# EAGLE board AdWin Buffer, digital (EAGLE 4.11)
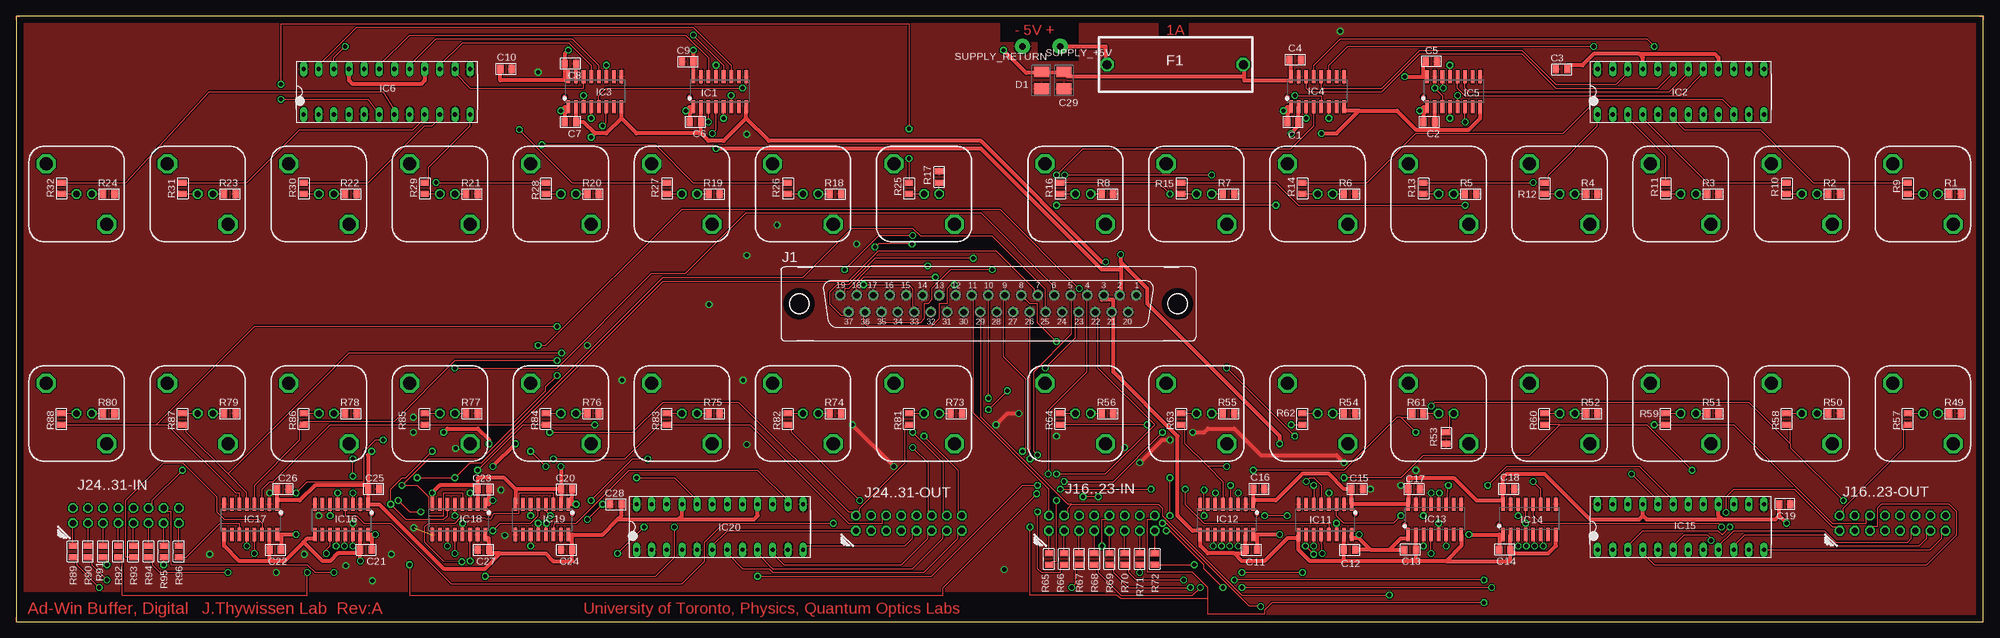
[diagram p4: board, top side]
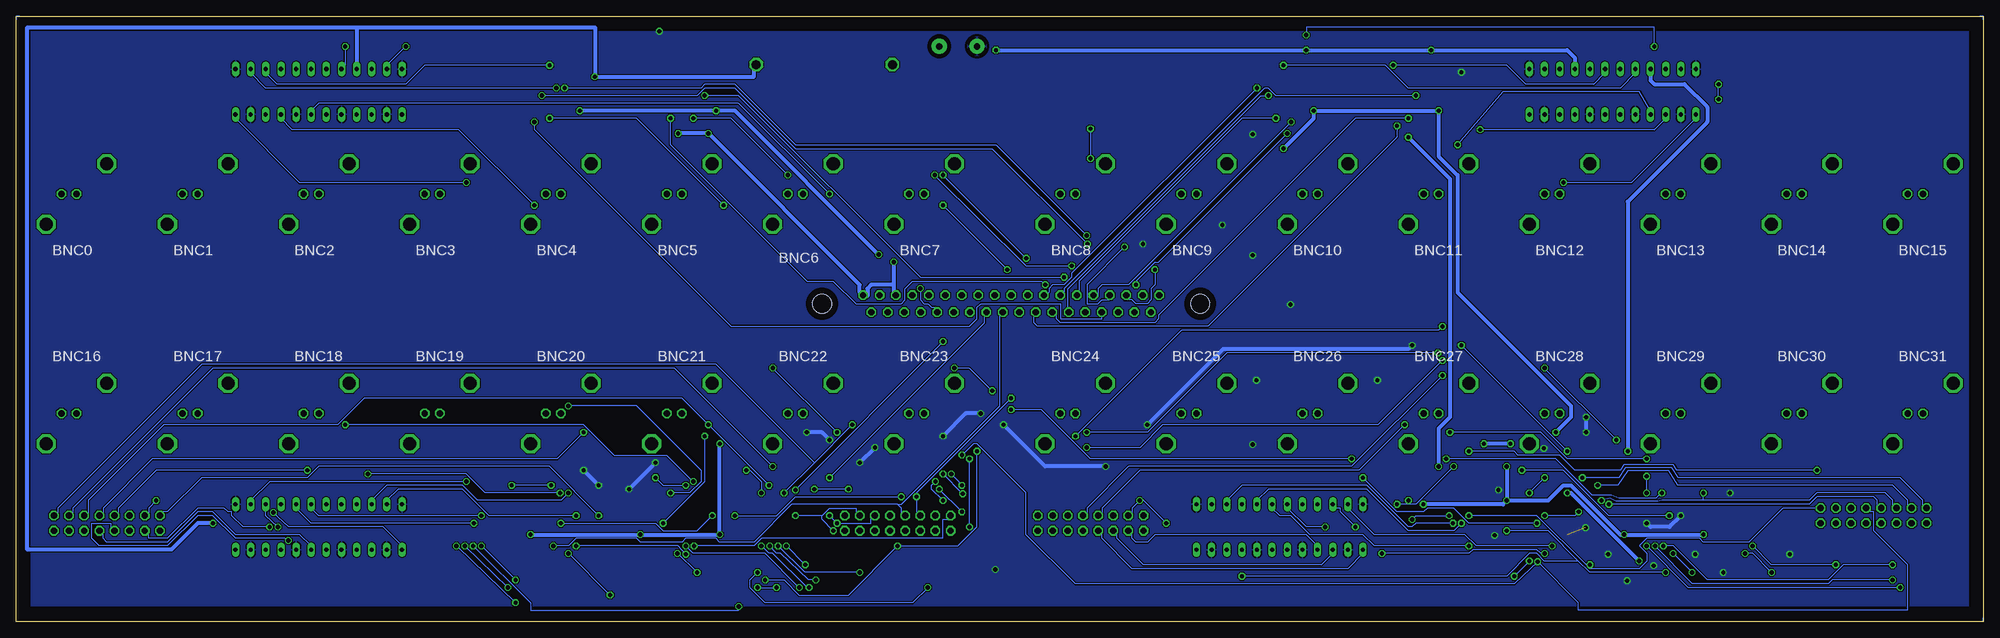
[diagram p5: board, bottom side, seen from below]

Size 330.2 x 101.6 mm. Coordinates in mm from the lower left corner, seen from the top.
Outline: 0,0 330.2,0 330.2,101.6 0,101.6 0,0
Copper layers (1*16): Top 0.035mm / dielectric 1.5mm / Bottom 0.035mm
Design rules "default": minimum track width 8mil, minimum drill 24mil, track to track 8mil, track to pad 8mil, pad to pad 8mil, via to via 8mil, smd to smd 8mil, copper to edge 40mil, drill to drill 8mil, minimum pad ring 10mil, minimum via ring 8mil, stop-mask expansion 4mil, vias tented up to drill 0mil, thermal gap 10mil
Net classes: 1 Pwr/Gnd .016"w: width 0.406 mm; 2 Pwr/Gnd .025"w: width 0.635 mm

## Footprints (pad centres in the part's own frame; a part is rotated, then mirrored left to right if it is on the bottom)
CONN-BNC-AMPHENOL-TYPE1 = drill 1.067 octagon: CONDUCTOR 0,0; SHIELD -2.54,0 | drill 2.184 octagon: MTG1 -5.08,-5.08; MTG2 5.08,5.08
0805 = smd 1.016 x 1.397: 1 -1.905,0; 2 0,0
EIA-B = smd 1.778 x 2.54: 1 -1.4,0; 2 1.4,0
FUSE5X20-2 = drill 1.511 octagon: 1 -10.16,0; 2 12.7,0
SOIC-16 = smd 0.6 x 2.2: 1 -3.81,-2.54; 2 -2.54,-2.54; 3 -1.27,-2.54; 4 0,-2.54; 5 1.27,-2.54; 6 2.54,-2.54; 7 3.81,-2.54; 8 5.08,-2.54; 9 5.08,2.54; 10 3.81,2.54; 11 2.54,2.54; 12 1.27,2.54; 13 0,2.54; 14 -1.27,2.54; 15 -2.54,2.54; 16 -3.81,2.54
DIL24 = drill 0.711 long: 1 -11.43,-3.81; 2 -8.89,-3.81; 3 -6.35,-3.81; 4 -3.81,-3.81; 5 -1.27,-3.81; 6 1.27,-3.81; 7 3.81,-3.81; 8 6.35,-3.81; 9 8.89,-3.81; 10 11.43,-3.81; 11 13.97,-3.81; 12 16.51,-3.81; 13 16.51,3.81; 14 13.97,3.81; 15 11.43,3.81; 16 8.89,3.81; 17 6.35,3.81; 18 3.81,3.81; 19 1.27,3.81; 20 -1.27,3.81; 21 -3.81,3.81; 22 -6.35,3.81; 23 -8.89,3.81; 24 -11.43,3.81
F37V = drill 1.067 octagon: 1 24.841,1.422; 2 22.073,1.422; 3 19.329,1.422; 4 16.561,1.422; 5 13.792,1.422; 6 11.049,1.422; 7 8.28,1.422; 8 5.512,1.422; 9 2.769,1.422; 10 0,1.422; 11 -2.769,1.422; 12 -5.512,1.422; 13 -8.28,1.422; 14 -11.049,1.422; 15 -13.818,1.422; 16 -16.561,1.422; 17 -19.329,1.422; 18 -22.098,1.422; 19 -24.841,1.422; 20 23.47,-1.422; 21 20.701,-1.422; 22 17.932,-1.422; 23 15.189,-1.422; 24 12.421,-1.422; 25 9.652,-1.422; 26 6.909,-1.422; 27 4.14,-1.422; 28 1.372,-1.422; 29 -1.372,-1.422; 30 -4.14,-1.422; 31 -6.909,-1.422; 32 -9.677,-1.422; 33 -12.421,-1.422; 34 -15.189,-1.422; 35 -17.958,-1.422; 36 -20.701,-1.422; 37 -23.47,-1.422 | hole 3.175: 31.75,0; -31.75,0
JUMPER-2X8 = drill 1.067 octagon: 1 -1.27,7.62; 2 -1.27,5.08; 3 -1.27,2.54; 4 -1.27,0; 5 -1.27,-2.54; 6 -1.27,-5.08; 7 -1.27,-7.62; 8 -1.27,-10.16; 9 1.27,7.62; 10 1.27,5.08; 11 1.27,2.54; 12 1.27,0; 13 1.27,-2.54; 14 1.27,-5.08; 15 1.27,-7.62; 16 1.27,-10.16
TP-HOLE = drill 1.067 pad 2.54 round: P$1 0,0

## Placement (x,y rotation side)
BNC0  AMP 227673-1  [CONN-BNC-AMPHENOL-TYPE1]  320.04,71.75 0 bottom
BNC1  [CONN-BNC-AMPHENOL-TYPE1]  299.72,71.75 0 bottom
BNC2  [CONN-BNC-AMPHENOL-TYPE1]  279.4,71.75 0 bottom
BNC3  [CONN-BNC-AMPHENOL-TYPE1]  259.08,71.75 0 bottom
BNC4  [CONN-BNC-AMPHENOL-TYPE1]  238.76,71.75 0 bottom
BNC5  [CONN-BNC-AMPHENOL-TYPE1]  218.44,71.75 0 bottom
BNC6  [CONN-BNC-AMPHENOL-TYPE1]  198.12,71.75 0 bottom
BNC7  [CONN-BNC-AMPHENOL-TYPE1]  177.8,71.75 0 bottom
BNC8  AMP 227673-1  [CONN-BNC-AMPHENOL-TYPE1]  152.4,71.75 0 bottom
BNC9  [CONN-BNC-AMPHENOL-TYPE1]  132.08,71.75 0 bottom
BNC10  [CONN-BNC-AMPHENOL-TYPE1]  111.76,71.75 0 bottom
BNC11  [CONN-BNC-AMPHENOL-TYPE1]  91.44,71.75 0 bottom
BNC12  [CONN-BNC-AMPHENOL-TYPE1]  71.12,71.75 0 bottom
BNC13  [CONN-BNC-AMPHENOL-TYPE1]  50.8,71.75 0 bottom
BNC14  [CONN-BNC-AMPHENOL-TYPE1]  30.48,71.75 0 bottom
BNC15  [CONN-BNC-AMPHENOL-TYPE1]  10.16,71.75 0 bottom
BNC16  AMP 227673-1  [CONN-BNC-AMPHENOL-TYPE1]  320.04,34.92 0 bottom
BNC17  [CONN-BNC-AMPHENOL-TYPE1]  299.72,34.92 0 bottom
BNC18  [CONN-BNC-AMPHENOL-TYPE1]  279.4,34.92 0 bottom
BNC19  [CONN-BNC-AMPHENOL-TYPE1]  259.08,34.92 0 bottom
BNC20  [CONN-BNC-AMPHENOL-TYPE1]  238.76,34.92 0 bottom
BNC21  [CONN-BNC-AMPHENOL-TYPE1]  218.44,34.92 0 bottom
BNC22  [CONN-BNC-AMPHENOL-TYPE1]  198.12,34.92 0 bottom
BNC23  [CONN-BNC-AMPHENOL-TYPE1]  177.8,34.92 0 bottom
BNC24  AMP 227673-1  [CONN-BNC-AMPHENOL-TYPE1]  152.4,34.92 0 bottom
BNC25  [CONN-BNC-AMPHENOL-TYPE1]  132.08,34.92 0 bottom
BNC26  [CONN-BNC-AMPHENOL-TYPE1]  111.76,34.92 0 bottom
BNC27  [CONN-BNC-AMPHENOL-TYPE1]  91.44,34.92 0 bottom
BNC28  [CONN-BNC-AMPHENOL-TYPE1]  71.12,34.92 0 bottom
BNC29  [CONN-BNC-AMPHENOL-TYPE1]  50.8,34.92 0 bottom
BNC30  [CONN-BNC-AMPHENOL-TYPE1]  30.48,34.92 0 bottom
BNC31  [CONN-BNC-AMPHENOL-TYPE1]  10.16,34.92 0 bottom
C1  0.1uF  [0805]  213.36,83.82 180 top
C2  [0805]  236.22,83.82 180 top
C3  0.1uF  [0805]  260.35,92.71 0 top
C4  [0805]  213.74,94.23 180 top
C5  [0805]  236.6,93.98 180 top
C6  0.1uF  [0805]  113.03,83.82 180 top
C7  [0805]  92.08,83.82 180 top
C8  0.1uF  [0805]  92.08,93.6 180 top
C9  [0805]  113.67,93.98 0 top
C10  [0805]  81.28,92.71 180 top
C11  0.1uF  [0805]  208.28,12.06 0 top
C12  [0805]  224.79,12.06 0 top
C13  [0805]  233.04,12.06 180 top
C14  [0805]  248.92,12.06 180 top
C15  0.1uF  [0805]  224.16,22.23 180 top
C16  [0805]  207.65,22.23 180 top
C17  [0805]  233.68,22.23 180 top
C18  [0805]  249.56,22.23 180 top
C19  [0805]  295.91,19.68 180 top
C20  0.1uF  [0805]  93.34,22.23 0 top
C21  [0805]  59.69,12.06 0 top
C22  [0805]  44.45,12.06 0 top
C23  [0805]  79.38,22.23 0 top
C24  0.1uF  [0805]  93.34,12.06 0 top
C25  [0805]  59.05,22.23 180 top
C26  [0805]  43.81,22.23 180 top
C27  [0805]  79.38,12.06 0 top
C28  [0805]  101.6,19.68 0 top
C29  10uF  [EIA-B]  175.9,90.81 90 top
D1  1N????  [EIA-B]  172.09,90.81 90 top
F1  1A  [FUSE5X20-2]  195.83,93.47 180 top
IC1  [SOIC-16]  117.47,88.9 0 top
IC2  [DIL24]  276.86,88.9 0 top
IC3  [SOIC-16]  96.52,88.9 0 top
IC4  [SOIC-16]  217.81,88.9 0 top
IC5  [SOIC-16]  240.66,88.9 0 top
IC6  [DIL24]  59.69,88.9 0 top
IC11  [SOIC-16]  220.34,17.14 180 top
IC12  [SOIC-16]  203.84,17.14 180 top
IC13  [SOIC-16]  237.49,17.14 0 top
IC14  [SOIC-16]  253.37,17.14 0 top
IC15  [DIL24]  276.86,15.88 0 top
IC16  [SOIC-16]  55.24,17.14 180 top
IC17  [SOIC-16]  40.01,17.14 180 top
IC18  [SOIC-16]  74.93,17.14 180 top
IC19  [SOIC-16]  88.9,17.14 180 top
IC20  [DIL24]  115.57,15.88 0 top
J1  Wickmann #647  [F37V]  163.19,53.34 0 top
J16..23-IN  JUMPER-2X8  [JUMPER-2X8]  180.97,16.51 90 top
J16..23-OUT  JUMPER-2X8  [JUMPER-2X8]  313.69,16.51 90 top
J24..31-IN  JUMPER-2X8  [JUMPER-2X8]  17.14,17.78 90 top
J24..31-OUT  JUMPER-2X8  [JUMPER-2X8]  148.59,16.51 90 top
R1  4.3  [0805]  326.39,71.75 0 top
R2  4.3  [0805]  306.07,71.75 0 top
R3  4.3  [0805]  285.75,71.75 0 top
R4  4.3  [0805]  265.43,71.75 0 top
R5  4.3  [0805]  245.11,71.75 0 top
R6  4.3  [0805]  224.79,71.75 0 top
R7  4.3  [0805]  204.47,71.75 0 top
R8  4.3  [0805]  184.15,71.75 0 top
R9  43  [0805]  317.5,71.75 270 top
R10  43  [0805]  297.18,71.75 270 top
R11  43  [0805]  276.86,71.75 270 top
R12  43  [0805]  256.54,71.75 270 top
R13  43  [0805]  236.22,71.75 270 top
R14  43  [0805]  215.9,71.75 270 top
R15  43  [0805]  195.58,71.75 270 top
R16  43  [0805]  175.26,71.75 270 top
R17  4.3  [0805]  154.94,75.56 90 top
R18  4.3  [0805]  138.43,71.75 0 top
R19  4.3  [0805]  118.11,71.75 0 top
R20  4.3  [0805]  97.79,71.75 0 top
R21  4.3  [0805]  77.47,71.75 0 top
R22  4.3  [0805]  57.15,71.75 0 top
R23  4.3  [0805]  36.83,71.75 0 top
R24  4.3  [0805]  16.51,71.75 0 top
R25  43  [0805]  149.86,71.75 270 top
R26  43  [0805]  129.54,71.75 270 top
R27  43  [0805]  109.22,71.75 270 top
R28  43  [0805]  88.9,71.75 270 top
R29  43  [0805]  68.58,71.75 270 top
R30  43  [0805]  48.26,71.75 270 top
R31  43  [0805]  27.94,71.75 270 top
R32  43  [0805]  7.62,71.75 270 top
R49  4.3  [0805]  326.39,34.92 0 top
R50  4.3  [0805]  306.07,34.92 0 top
R51  4.3  [0805]  285.75,34.92 0 top
R52  4.3  [0805]  265.43,34.92 0 top
R53  4.3  [0805]  240.03,29.84 270 top
R54  4.3  [0805]  224.79,34.92 0 top
R55  4.3  [0805]  204.47,34.92 0 top
R56  4.3  [0805]  184.15,34.92 0 top
R57  43  [0805]  317.5,34.92 90 top
R58  43  [0805]  297.18,34.92 90 top
R59  43  [0805]  276.86,34.92 90 top
R60  43  [0805]  256.54,34.92 90 top
R61  43  [0805]  236.22,34.92 0 top
R62  43  [0805]  215.9,34.92 90 top
R63  43  [0805]  195.58,34.92 90 top
R64  43  [0805]  175.26,34.92 90 top
R65  2K  [0805]  173.35,11.43 90 top
R66  [0805]  175.9,11.43 90 top
R67  [0805]  178.44,11.43 90 top
R68  [0805]  180.97,11.43 90 top
R69  [0805]  183.51,11.43 90 top
R70  [0805]  186.06,11.43 90 top
R71  [0805]  188.59,11.43 90 top
R72  [0805]  191.13,11.43 90 top
R73  4.3  [0805]  158.75,34.92 0 top
R74  4.3  [0805]  138.43,34.92 0 top
R75  4.3  [0805]  118.11,34.92 0 top
R76  4.3  [0805]  97.79,34.92 0 top
R77  4.3  [0805]  77.47,34.92 0 top
R78  4.3  [0805]  57.15,34.92 0 top
R79  4.3  [0805]  36.83,34.92 0 top
R80  4.3  [0805]  16.51,34.92 0 top
R81  43  [0805]  149.86,34.92 90 top
R82  43  [0805]  129.54,34.92 90 top
R83  43  [0805]  109.22,34.92 90 top
R84  43  [0805]  88.9,34.92 90 top
R85  43  [0805]  68.58,34.92 90 top
R86  43  [0805]  48.26,34.92 90 top
R87  43  [0805]  27.94,34.92 90 top
R88  43  [0805]  7.62,34.92 90 top
R89  2K  [0805]  9.53,12.7 90 top
R90  [0805]  12.06,12.7 90 top
R91  [0805]  14.61,12.7 90 top
R92  [0805]  17.14,12.7 90 top
R93  [0805]  19.68,12.7 90 top
R94  [0805]  22.23,12.7 90 top
R95  [0805]  24.77,12.7 90 top
R96  [0805]  27.3,12.7 90 top
SUPPLY_+5V  [TP-HOLE]  175.26,96.52 0 top
SUPPLY_RETURN  [TP-HOLE]  168.91,96.52 0 top
U$5  [TARGET]  not placed on the board
U$7  [TARGET]  not placed on the board
U$8  [TARGET]  not placed on the board
U$9  [TITLEBLOCK_PCB]  not placed on the board

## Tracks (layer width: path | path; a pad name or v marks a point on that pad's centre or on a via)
+5V  (via drill 0.71)
  Top 0.635: 295.91,17.78 295.27,17.14 286.38,17.14 | 286.38,17.14 285.75,17.78 IC15.16 | 295.91,17.78 C19.2 | 273.05,17.78 273.69,17.14 286.38,17.14 | 273.05,17.78 IC15.21 | 249.56,20.32 C18.2 249.56,24.13 250.19,24.77 256.54,24.77 264.16,17.14 272.42,17.14 273.05,17.78 | 207.65,20.32 C16.2 | 207.65,20.32 211.46,20.32 215.9,24.77 220.34,24.77 222.88,22.23 C15.2 IC11.1 IC13.16 C17.2 233.68,24.13 241.3,24.13 245.11,20.32 249.56,20.32 | 207.65,20.32 IC12.1 | 249.56,20.32 IC14.16 | 43.81,20.32 C26.2 | 43.81,20.32 47.62,20.32 50.16,22.86 59.05,22.86 | 43.81,20.32 IC17.1 | IC18.16 78.74,13.97 79.38,13.97 C27.2 79.38,11.43 81.28,11.43 | 93.34,14.61 IC19.16 | 93.34,14.61 C24.2 93.34,10.16 90.17,10.16 88.9,11.43 81.28,11.43 | 100.97,17.14 98.42,14.61 93.34,14.61 | 100.97,17.14 101.6,17.78 C28.2 | 111.12,17.14 111.76,17.78 IC20.21 | 100.97,17.14 111.12,17.14 | 111.12,17.14 123.83,17.14 124.46,17.78 IC20.16 | 81.28,11.43 78.74,8.89 71.75,8.89 60.96,19.68 IC16.1 C25.2 59.05,22.86 | IC6.21 55.88,90.81 56.52,90.17 67.94,90.17 68.58,90.81 IC6.16 | IC1.16 C9.2 v113.67,95.89 | 92.08,90.81 92.71,90.81 IC3.16 | 92.08,90.81 81.28,90.81 C10.2 | 92.08,90.81 C8.2 92.08,95.25 v92.71,95.89 | 272.42,95.25 264.8,95.25 262.89,93.34 260.35,93.34 C3.2 | 272.42,95.25 273.05,94.61 IC2.21 | 272.42,95.25 285.12,95.25 285.75,94.61 IC2.16 | 236.22,91.44 236.22,93.34 C5.2 | 236.22,91.44 IC5.16 | C4.2 214,93.34 IC4.16 214,90.81 206.12,90.81 206.08,91.57 | F1.1 206.08,91.57 | v233.04,91.44 236.22,91.44 | v165.74,95.89 169.54,92.08 171.45,92.08 D1.2 172.72,92.08 175.26,92.08 C29.2 176.53,91.44 205.99,91.44 206.08,91.57 | 59.05,22.86 59.05,27.94 v59.69,28.57
  Top 0.635: 295.91,17.78 v297.18,16.51
  Bottom 0.635: IC6.16 68.58,94.61 69.85,95.89 v92.71,95.89 v113.67,95.89 v165.74,95.89 | 273.05,99.69 233.04,99.69 v233.04,91.44 206.38,91.44 206.38,93.34 F1.1 | 273.05,99.69 IC2.21 | v59.69,28.57 59.69,70.48 46.35,83.82 46.35,86.36 50.16,90.17 55.24,90.17 55.88,90.81 IC6.21 | v297.18,16.51 299.72,16.51 304.17,12.06 328.3,12.06 328.3,99.69 273.05,99.69
AGND  (via drill 0.71)  (1 unrouted)
  Top 0.635: v222.88,26.67 221.62,27.94 208.91,27.94 204.47,32.38 200.03,32.38 199.39,31.75 v197.49,31.75 | v193.68,30.48 192.41,30.48 v188.59,26.67 | v168.28,34.92 166.37,34.92 v164.47,33.02 | v140.34,33.02 v147.32,26.04
  Bottom 0.635: v232.41,22.86 v234.95,25.4 | v222.88,26.67 v227.33,22.23 | v197.49,31.75 194.94,31.75 v193.68,30.48 | v186.06,29.21 v188.59,26.67 | v174.62,31.11 170.81,34.92 v168.28,34.92 | v164.47,33.02 157.48,26.04 v147.32,26.04 | v140.34,33.02 127.64,45.72 96.52,45.72 v95.89,46.35 | v66.67,31.75 v66.67,34.29 | v50.8,17.78 52.7,15.88 55.88,15.88 v56.52,16.51
  other vias: 42.55,21.59 222.25,99.06 116.31,53.2 122.66,61.46 122.03,40.5 101.71,40.5 122.66,29.71 127.74,66.54 87.61,92.19 122.66,81.78 141.08,63.36 165.84,8.75 62.97,11.29 59.8,6.85 32.49,11.29 48.37,11.29 82.02,14.47 73.77,29.07 55.35,9.39 43.67,8.24 66.78,15.74 81.39,22.09
  pour Top: 1.27,100.33 1.27,5.08 182.88,5.08 182.88,1.27 328.93,1.27 328.93,100.33 196.85,100.33 196.85,97.79 191.77,97.79 191.77,100.33 178.44,100.33 178.44,93.98 171.45,93.98 171.45,97.16 165.1,97.16 165.1,100.33
  pour Bottom: 2.54,99.06 2.54,2.54 327.66,2.54 327.66,99.06
BNC0
  Top 0.203: R9.1 301.62,73.66 292.74,82.55 280.04,82.55 278.13,84.45 IC2.6
BNC1
  Top 0.203: R10.1 283.85,73.66 273.05,84.45 IC2.4
BNC2
  Top 0.203: R11.1 276.86,78.11 270.51,84.45 IC2.3
BNC3
  Top 0.203: R12.1 257.18,73.66 257.18,74.93 265.43,83.19 IC2.1
BNC4  (via drill 0.71)
  Top 0.203: R13.1 v254.63,73.66
  Bottom 0.203: v254.63,73.66 282.57,73.66 293.37,84.45 IC2.12
BNC5
  Top 0.203: R14.1 226.69,73.66 234.95,81.92 259.71,81.92 265.43,87.63 286.38,87.63 288.29,85.72 IC2.10
BNC6  (via drill 0.71)
  Top 0.203: v243.21,69.85 215.26,69.85 211.46,73.66 R15.1
  Bottom 0.203: v243.21,69.85 255.91,82.55 283.85,82.55 285.75,84.45 IC2.9
BNC7  (via drill 0.71)
  Top 0.203: v193.68,71.75 191.77,73.66 R16.1
  Bottom 0.203: v193.68,71.75 208.91,87 279.4,87 280.67,85.72 IC2.7
BNC8  (via drill 0.71)
  Top 0.203: v149.86,82.68 149.86,100.33 44.45,100.33 v44.45,90.17 | v149.86,77.72 R25.1 | v44.45,87.63 59.05,87.63 IC6.6
  Bottom 0.203: v44.45,87.63 v44.45,90.17 | v149.86,82.68 v149.86,77.72
BNC9  (via drill 0.71)
  Top 0.203: v88.27,80.01 107.31,80.01 113.67,73.66 R26.1
  Bottom 0.203: v88.27,80.01 80.64,88.9 57.78,88.9 55.88,85.72 IC6.4
BNC10  (via drill 0.71)
  Top 0.203: v84.45,82.55 93.34,73.66 R27.1
  Bottom 0.203: v84.45,82.55 55.24,82.55 53.34,84.45 IC6.3
BNC11  (via drill 0.71)
  Top 0.203: v70.48,73.66 R28.1
  Bottom 0.203: v70.48,73.66 59.05,73.66 48.26,84.45 IC6.1
BNC12
  Top 0.203: R29.1 69.22,73.66 69.22,76.2 76.2,83.19 IC6.12
BNC13
  Top 0.203: R30.1 59.05,73.66 68.58,83.19 69.85,83.19 71.12,84.45 IC6.10
BNC14
  Top 0.203: R31.1 38.73,73.66 47.62,82.55 66.67,82.55 68.58,84.45 IC6.9
BNC15
  Top 0.203: R32.1 18.41,73.66 32.38,88.9 61.59,88.9 63.5,85.72 IC6.7
BNC16  (via drill 0.71)
  Top 0.203: R57.1 316.87,33.02 316.87,29.21 306.7,19.05 306.7,17.78 J16..23-OUT.9 | v232.41,17.78 231.14,16.51 222.88,16.51 221.62,17.78 IC11.3
  Bottom 0.203: v232.41,17.78 240.66,26.04 279.4,26.04 281.31,24.13 299.08,24.13 304.8,18.41 306.07,18.41 J16..23-OUT.9
BNC17  (via drill 0.71)
  Top 0.203: 297.81,29.84 297.81,29.21 v306.7,20.32 | 297.81,29.84 297.81,33.02 R58.1 | v237.49,36.2 238.12,36.83 290.83,36.83 297.81,29.84 | v220.34,21.59 IC11.4
  Bottom 0.203: v306.7,20.32 307.98,19.05 307.98,17.78 J16..23-OUT.10 | v220.34,21.59 217.17,21.59 215.26,23.5 215.26,25.4 226.06,36.2 v237.49,36.2
BNC18  (via drill 0.71)
  Top 0.203: J16..23-OUT.11 310.51,17.78 310.51,16.51 304.8,16.51 288.29,33.02 R59.1 v274.95,33.02 | v216.53,23.5 217.17,24.13 217.81,24.13 219.07,22.86 IC11.5
  Bottom 0.203: v216.53,23.5 220.98,27.94 229.87,27.94 234.95,33.02 v274.95,33.02
BNC19  (via drill 0.71)
  Top 0.203: 259.08,33.02 273.69,33.02 v281.31,25.4 | 259.08,33.02 R60.1 | v222.88,24.13 232.41,24.13 236.22,27.94 254,27.94 259.08,33.02 | v217.81,22.86 IC11.6
  Bottom 0.203: v281.31,25.4 306.7,25.4 313.06,19.05 313.06,17.78 J16..23-OUT.12 | v217.81,22.86 221.62,22.86 v222.88,24.13
BNC20  (via drill 0.71)
  Top 0.203: 232.41,34.29 231.78,34.29 222.88,25.4 v207.65,25.4 | 232.41,34.29 234.31,34.29 R61.1 | v205.1,21.59 IC12.3 | v234.95,31.75 232.41,34.29
  Bottom 0.203: v207.65,25.4 207.01,25.4 205.1,23.5 v205.1,21.59 | v234.95,31.75 239.4,27.3 307.34,27.3 315.6,19.05 315.6,17.78 J16..23-OUT.13
BNC21  (via drill 0.71)
  Top 0.203: v214,33.02 R62.1 | v203.84,22.86 IC12.4
  Bottom 0.203: v203.84,22.86 v214,33.02 218.44,37.47 271.78,37.47 276.23,33.02 305.44,33.02 318.13,20.32 318.13,17.78 J16..23-OUT.14
BNC22  (via drill 0.71)
  Top 0.203: 200.03,26.04 202.56,23.5 IC12.5 | 200.03,26.04 196.22,29.84 196.22,33.02 R63.1 | v203.2,26.04 200.03,26.04
  Bottom 0.203: v203.2,26.04 219.71,42.55 297.18,42.55 320.68,19.05 320.68,17.78 J16..23-OUT.15
BNC23  (via drill 0.71)
  Top 0.203: v189.87,33.02 R64.1 | v201.29,21.59 IC12.6
  Bottom 0.203: 196.22,26.67 v201.29,21.59 | 196.22,26.67 v189.87,33.02 | 196.22,26.67 212.72,43.18 299.08,43.18 323.21,19.05 323.21,17.78 J16..23-OUT.16
BNC24  (via drill 0.71)
  Top 0.203: R81.1 149.22,33.02 149.22,26.67 141.6,19.05 141.6,17.78 J24..31-OUT.9 140.97,18.41 139.7,18.41 121.28,36.83 108.58,36.83 103.5,31.75 v89.53,31.75 | v56.52,24.38 v56.52,27.3 | IC16.3 v56.52,21.59
  Bottom 0.203: v56.52,27.3 69.85,27.3 74.3,31.75 v89.53,31.75 | v56.52,21.59 v56.52,24.38
BNC25  (via drill 0.71)
  Top 0.203: v141.6,20.32 130.18,31.75 130.18,33.02 R82.1 | v137.16,16.51 118.75,16.51 115.57,13.34 115.57,10.16 111.76,6.35 73.03,6.35 62.87,16.51 58.42,16.51 57.15,17.78 55.24,17.78 IC16.4
  Bottom 0.203: J24..31-OUT.10 142.88,17.78 142.88,19.05 v141.6,20.32 140.97,20.32 v137.16,16.51
BNC26  (via drill 0.71)
  Top 0.203: J24..31-OUT.11 145.41,17.78 145.41,16.51 139.7,16.51 123.19,33.02 R83.1 107.95,33.02 102.23,27.3 v90.17,27.3 | IC16.5 v53.98,21.59
  Bottom 0.203: v53.98,21.59 54.99,20.7 61.21,20.7 62.48,21.21 65.66,21.21 71.75,27.3 v90.17,27.3
BNC27  (via drill 0.71)
  Top 0.203: v77.47,25.4 85.09,33.02 R84.1 v97.16,33.02 | IC16.6 v52.7,17.78
  Bottom 0.203: v77.47,25.4 70.48,25.4 62.87,17.78 v52.7,17.78 | v97.16,33.02 104.78,25.4 141.6,25.4 147.96,19.05 147.96,17.78 J24..31-OUT.12
BNC28  (via drill 0.71)
  Top 0.203: IC17.3 41.27,22.23 42.55,23.5 43.18,23.5 52.7,33.02 R85.1 83.19,33.02 88.9,38.73 88.9,39.37 v90.81,41.27
  Bottom 0.203: v90.81,41.27 106.05,26.04 143.51,26.04 150.5,19.05 150.5,17.78 J24..31-OUT.13
BNC29  (via drill 0.71)
  Top 0.203: 47.62,33.02 47.62,30.48 40.01,22.86 IC17.4 | v150.5,29.21 153.03,26.67 153.03,17.78 J24..31-OUT.14 | v90.81,43.81 73.66,43.81 63.5,33.66 48.26,33.66 47.62,33.02 | 47.62,33.02 R86.1
  Bottom 0.203: v150.5,29.21 141.6,29.21 137.79,33.02 101.6,33.02 v90.81,43.81
BNC30  (via drill 0.71)
  Top 0.203: 35.56,24.77 38.73,21.59 IC17.5 | 35.56,24.77 28.57,31.75 28.57,33.02 R87.1 | v150.5,31.75 155.57,26.67 155.57,17.78 J24..31-OUT.15 | v91.57,45.09 55.88,45.09 35.56,24.77
  Bottom 0.203: v150.5,31.75 140.34,31.75 127,45.09 v91.57,45.09
BNC31  (via drill 0.71)
  Top 0.203: 23.5,33.02 25.4,33.02 36.83,21.59 37.47,21.59 IC17.6 | R88.1 23.5,33.02 | v152.4,31.11 158.12,25.4 158.12,17.78 J24..31-OUT.16 | v90.81,49.53 40.01,49.53 23.5,33.02
  Bottom 0.203: v152.4,31.11 134.62,48.9 91.44,48.9 v90.81,49.53
D0  (via drill 0.71)
  Top 0.203: v200.66,74.93 v176.02,74.93 | v153.03,59.69 143.51,59.69 139.7,55.88 139.06,55.88 139.06,54.61 J1.19 | v216.53,84.45 IC4.3
  Bottom 0.203: v216.53,84.45 210.19,84.45 v200.66,74.93 | v176.02,74.93 160.66,59.69 v153.03,59.69
D1  (via drill 0.71)
  Top 0.203: v174.62,74.93 179.07,79.38 214,79.38 217.81,83.19 IC4.4 | v160.66,60.96 144.15,60.96 139.7,56.52 137.79,56.52 136.53,55.24 136.53,53.34 138.43,51.44 139.7,51.44 J1.37
  Bottom 0.203: v174.62,74.93 v160.66,60.96
D2  (via drill 0.71)
  Top 0.203: v214.63,88.27 219.07,88.27 IC4.5 | v154.31,57.78 142.24,57.78 140.97,56.52 140.97,55.24 J1.18
  Bottom 0.203: v214.63,88.27 208.91,88.27 178.44,57.78 v154.31,57.78
D3  (via drill 0.71)
  Top 0.203: v157.48,56.52 156.84,56.52 156.21,55.88 156.21,53.34 154.94,53.34 154.94,50.8 153.67,49.53 142.88,49.53 142.24,50.16 142.24,51.44 J1.36 | v220.34,84.45 IC4.6
  Bottom 0.203: v220.34,84.45 220.34,80.01 197.49,57.15 193.04,57.15 189.23,53.34 181.61,53.34 180.97,53.98 180.97,55.88 179.71,57.15 158.12,57.15 v157.48,56.52
D4  (via drill 0.71)
  Top 0.203: v238.12,89.53 239.4,88.27 IC5.3 | v150.5,64.77 144.78,64.77 v139.06,59.05
  Bottom 0.203: v238.12,89.53 215.26,89.53 214.63,90.17 209.55,90.17 199.39,80.01 165.74,80.01 v150.5,64.77 | v139.06,59.05 139.06,56.52 139.7,55.88 139.7,53.98 140.34,53.34 142.24,53.34 142.88,53.98 144.15,53.98 J1.17
D5  (via drill 0.71)
  Top 0.203: v211.46,69.85 v174.62,69.85 | v163.83,59.05 156.84,59.05 153.67,55.88 153.67,53.98 153.03,53.34 152.4,53.34 152.4,50.8 151.76,50.16 145.41,50.16 145.41,51.44 J1.35 | v240.66,84.45 IC5.4
  Bottom 0.203: v240.66,84.45 226.06,84.45 v211.46,69.85 | v174.62,69.85 v163.83,59.05
D6  (via drill 0.71)
  Top 0.203: v150.37,63.37 144.78,63.37 v144.15,62.87 | v241.94,88.27 IC5.5
  Bottom 0.203: v241.94,88.27 215.9,88.27 214.63,89.53 209.55,89.53 199.39,79.38 166.37,79.38 v150.37,63.37 | v144.15,62.87 150.5,56.52 150.5,53.34 148.59,53.34 147.96,53.98 146.69,53.98 J1.16
D7  (via drill 0.71)
  Top 0.203: v243.21,83.82 IC5.6
  Bottom 0.203: v243.21,83.82 243.21,82.55 210.19,49.53 170.18,49.53 168.91,50.8 168.91,52.7 168.28,53.34 154.94,53.34 154.94,50.8 147.96,50.8 147.96,51.44 J1.34
D8  (via drill 0.71)
  Top 0.203: v116.2,83.82 IC1.3
  Bottom 0.203: v116.2,83.82 143.51,56.52 147.96,56.52 148.59,55.88 148.59,54.61 J1.15
D9  (via drill 0.71)
  Top 0.203: v116.84,81.92 117.47,82.55 IC1.4 | v142.24,56.52 149.86,56.52 150.5,55.88 150.5,52.7 J1.33
  Bottom 0.203: v116.84,81.92 138.43,60.33 139.06,60.33 142.24,57.15 v142.24,56.52
D10  (via drill 0.71)
  Top 0.203: v118.75,84.45 IC1.5
  Bottom 0.203: v118.75,84.45 124.46,84.45 151.76,57.15 151.76,55.24 J1.14
D11  (via drill 0.71)
  Top 0.203: v120.02,88.27 IC1.6
  Bottom 0.203: v120.02,88.27 121.28,88.27 153.67,55.88 153.67,52.7 J1.32
D12  (via drill 0.71)
  Top 0.203: IC3.3 v95.25,88.27
  Bottom 0.203: v95.25,88.27 118.75,88.27 120.02,89.53 120.65,89.53 154.31,55.88 154.31,55.24 J1.13
D13  (via drill 0.71)
  Top 0.203: v96.52,84.45 IC3.4
  Bottom 0.203: v96.52,84.45 105.41,84.45 138.43,51.44 138.43,50.8 139.06,50.16 154.94,50.16 155.57,50.8 155.57,52.07 J1.31
D14  (via drill 0.71)
  Top 0.203: v121.92,89.53 99.06,89.53 97.79,88.27 IC3.5
  Bottom 0.203: v121.92,89.53 153.03,58.42 153.03,57.78 154.31,56.52 156.21,56.52 156.84,55.88 156.84,55.24 157.48,54.61 J1.12
D15  (via drill 0.71)
  Top 0.203: v98.42,83.19 99.06,83.82 IC3.6
  Bottom 0.203: v98.42,83.19 98.42,81.28 130.18,49.53 158.75,49.53 159.38,50.16 159.38,51.44 J1.30
D16  (via drill 0.71)
  Top 0.203: v216.41,12.7 v217.81,11.3 | v236.22,12.7 IC13.3 | J1.11 160.66,53.98 160.66,34.92 173.35,22.23 J16..23-IN.9
  Bottom 0.203: v236.22,12.7 219.07,12.7 v217.81,11.3 | v216.41,12.7 206.38,12.7 205.1,13.97 174.62,13.97 174.62,17.14 173.35,17.14 J16..23-IN.9
D17  (via drill 0.71)
  Top 0.203: v230.5,4.45 205.74,4.45 192.41,17.78 192.41,19.05 191.77,19.68 177.16,19.68 | 177.16,19.68 176.53,19.05 176.53,17.78 J16..23-IN.10 | v237.49,11.43 IC13.4 | 177.16,19.68 176.53,19.68 161.93,34.29 161.93,51.44 J1.29
  Bottom 0.203: v230.5,4.45 v237.49,11.43
D18  (via drill 0.71)
  Top 0.203: v213.36,17.78 v209.55,17.78 | v181.61,20.95 v179.07,20.95 | v238.76,16.51 IC13.5 | v163.19,37.47 J1.10
  Bottom 0.203: v238.76,16.51 222.88,16.51 221.62,15.24 215.9,15.24 v213.36,17.78 | v209.55,17.78 202.56,17.78 199.39,20.95 v181.61,20.95 | J16..23-IN.11 179.07,17.78 v179.07,20.95 179.07,21.59 v163.19,37.47
D19  (via drill 0.71)
  Top 0.203: v240.03,12.7 IC13.6
  Bottom 0.203: v240.03,12.7 237.49,12.7 236.22,13.97 226.06,13.97 225.43,13.34 218.44,13.34 217.81,13.97 212.72,13.97 212.09,13.34 206.38,13.34 200.03,19.68 182.25,19.68 | 182.25,19.68 181.61,19.05 181.61,17.78 J16..23-IN.12 | 182.25,19.68 181.61,19.68 165.1,36.2 165.1,51.44 J1.28
D20  (via drill 0.71)
  Top 0.203: v246.38,6.99 v204.47,6.99 | v182.25,12.7 182.25,17.14 183.51,17.14 J16..23-IN.13 | IC14.3 v252.09,12.7 | v168.91,28.57 169.54,29.21 169.54,40.64 165.74,44.45 165.74,53.98 J1.9
  Bottom 0.203: v252.09,12.7 v246.38,6.99 | v204.47,6.99 201.29,6.99 198.75,4.45 190.5,4.45 v182.25,12.7 172.09,12.7 168.91,15.88 v168.91,28.57
D21  (via drill 0.71)
  Top 0.203: v208.91,2.54 207.01,2.54 193.04,16.51 v192.41,16.51 | IC14.4 v253.49,12.7 | v193.68,17.78 v193.68,24.13
  Bottom 0.203: v253.49,12.7 243.84,3.17 243.84,1.91 208.91,1.91 v208.91,2.54 | J16..23-IN.14 186.69,17.78 186.69,16.51 v192.41,16.51 v193.68,17.78 | v193.68,24.13 167.64,50.16 167.64,51.44 J1.27
D22  (via drill 0.71)
  Top 0.203: v247.65,5.71 v205.74,5.71 | v202.56,5.71 199.39,8.89 199.39,9.53 193.68,15.24 v193.04,15.24 | IC14.5 v254.89,12.7 | v174.62,46.99 171.45,50.16 171.45,53.34 170.18,53.34 169.54,53.98 168.91,53.98 J1.8 | v199.39,17.78 v199.39,22.1
  Bottom 0.203: v254.89,12.7 v247.65,5.71 | v205.74,5.71 v202.56,5.71 | v193.04,15.24 194.94,17.14 194.94,17.78 | 194.94,17.78 193.68,19.05 189.23,19.05 189.23,17.78 J16..23-IN.15 | v199.39,22.1 v174.62,46.99 | 194.94,17.78 v199.39,17.78
D23  (via drill 0.71)
  Top 0.203: v246.38,3.17 210.82,3.17 209.55,1.91 209.55,1.27 200.03,1.27 200.03,3.81 | 200.03,3.81 200.03,5.71 197.49,8.26 189.87,8.26 189.87,17.14 191.13,17.14 J16..23-IN.16 | IC14.6 v256.29,12.7 | v170.18,27.3 170.18,51.44 J1.26 | v170.18,15.88 170.18,4.45 184.78,4.45 185.42,3.81 200.03,3.81
  Bottom 0.203: v256.29,12.7 v246.38,3.17 | v170.18,15.88 v170.18,27.3
D24  (via drill 0.71)
  Top 0.203: v67.31,24.13 v73.66,24.13 76.2,26.67 78.11,26.67 108.58,57.15 139.7,57.15 144.78,62.23 164.47,62.23 170.81,55.88 170.81,54.61 J1.7 | v76.2,21.59 IC18.3
  Bottom 0.203: v73.66,24.13 v76.2,21.59 | v67.31,24.13 61.21,24.13 60.07,25.78 52.32,25.78 51.18,24.13 13.97,24.13 10.16,20.32 10.16,19.05 J24..31-IN.9
D25  (via drill 0.71)
  Top 0.203: IC18.4 74.93,21.59 71.75,21.59 71.75,17.78 69.22,17.78 69.22,20.95 67.31,22.86 v64.77,22.86 69.22,27.3 78.11,27.3 108.58,57.78 132.08,57.78 140.34,66.04 150.5,66.04 151.76,64.77 163.83,64.77 172.72,55.88 172.72,52.7 J1.25
  Bottom 0.203: v64.77,22.86 61.34,22.86 59.69,25.27 52.83,25.27 51.31,22.86 15.24,22.86 12.7,20.32 12.7,19.05 J24..31-IN.10
D26  (via drill 0.71)
  Top 0.203: v67.94,18.41 66.04,18.41 v64.14,20.32 | v73.66,17.78 IC18.5 | v73.66,42.55 90.81,42.55 106.68,58.42 112.39,58.42 122.56,68.58 161.93,68.58 173.99,56.52 173.99,55.24 J1.6 | v61.59,30.48 60.33,30.48 58.42,28.57 58.42,23.5 48.9,23.5 v46.99,21.59
  Bottom 0.203: v73.66,17.78 68.58,17.78 v67.94,18.41 | v64.14,20.32 62.74,20.7 61.72,20.19 54.61,20.19 53.98,20.32 46.99,20.32 | 46.99,20.32 29.21,20.32 27.94,21.59 16.51,21.59 15.24,20.32 15.24,19.05 J24..31-IN.11 | v61.59,30.48 v73.66,42.55 | 46.99,20.32 v46.99,21.59
D27  (via drill 0.71)
  Top 0.203: IC18.6 72.39,17.78 71.75,17.14 65.41,17.14 v62.87,19.68 62.87,22.23 64.77,24.13 65.41,24.13 v69.85,28.57 | v178.44,55.88 165.1,69.22 111.76,69.22 88.9,46.35 v87.63,46.35
  Bottom 0.203: v62.87,19.68 29.21,19.68 27.94,20.95 18.41,20.95 17.78,20.32 17.78,19.05 J24..31-IN.12 | v178.44,55.88 178.44,53.98 177.8,53.34 177.16,53.34 176.53,52.7 175.9,52.7 J1.24 | v69.85,28.57 v87.63,46.35
D28  (via drill 0.71)
  Top 0.203: v74.8,10.03 71.75,10.16 68.58,13.34 68.58,15.88 69.22,16.51 73.66,16.51 74.55,17.4 78.61,17.4 78.87,17.27 79.76,17.27 80.26,18.16 84.45,18.16 84.45,21.59 90.17,21.59 IC19.3 | v171.45,27.94 170.81,28.57 170.81,41.91 177.16,48.26 177.16,53.98 J1.5
  Bottom 0.203: J24..31-IN.13 19.68,18.41 18.41,18.41 18.41,15.24 12.7,9.53 12.7,1.91 67.94,1.91 67.94,3.17 v74.8,10.03 78.74,6.35 152.4,6.35 160.66,14.61 160.66,21.59 168.91,29.84 169.54,29.84 v171.45,27.94
D29  (via drill 0.71)
  Top 0.203: v98.42,19.68 v95.89,17.14 | v86.36,28.57 v88.9,26.04 | v27.94,25.4 22.86,20.32 22.86,19.05 J24..31-IN.14 | v89.66,17.78 88.9,18.67 IC19.4 | v172.72,42.55 177.8,47.62 177.8,51.44 J1.23 | v163.19,35.56 v166.37,38.73 | v106.05,27.3 103.5,27.3 v96.52,20.32
  Bottom 0.203: v89.66,17.78 95.25,17.78 v95.89,17.14 | 96.52,19.68 95.25,19.68 v88.9,26.04 | 96.52,19.68 v98.42,19.68 | v86.36,28.57 78.74,28.57 78.11,27.94 71.12,27.94 68.58,25.4 60.96,25.4 60.33,26.29 52.07,26.29 51.44,25.4 v27.94,25.4 | v172.72,42.55 170.18,42.55 v166.37,38.73 | v163.19,35.56 158.12,35.56 149.86,27.3 v106.05,27.3 | 96.52,19.68 v96.52,20.32
D30  (via drill 0.71)
  Top 0.203: v80.01,15.24 81.28,16.51 86.36,16.51 87.63,17.78 IC19.5 | v53.34,8.26 50.16,8.26 48.9,9.53 26.04,9.53 26.04,18.41 24.77,18.41 J24..31-IN.15 | v173.23,24.77 173.35,25.02 173.35,35.56 179.71,41.91 179.71,53.98 J1.4 | v171.45,22.86 168.91,22.86 153.67,7.62 v124.46,7.62
  Bottom 0.203: v80.01,15.24 73.03,15.24 67.94,10.16 | 67.94,10.16 66.04,8.26 v53.34,8.26 | v171.45,22.86 v173.23,24.77 | v124.46,7.62 80.01,7.62 76.2,11.43 74.93,11.43 73.66,10.16 67.94,10.16
D31  (via drill 0.71)
  Top 0.203: v86.36,17.78 IC19.6 | v174.62,24.77 182.88,24.77 191.13,33.02 181.61,42.55 181.61,51.44 J1.22 | v171.32,21.46 155.57,5.71 155.57,4.45 66.04,4.45 v66.04,9.53
  Bottom 0.203: v86.36,17.78 74.93,17.78 66.67,9.53 | 66.67,9.53 66.04,8.89 57.78,8.89 56.52,10.16 56.52,11.43 57.78,12.7 56.52,13.97 47.62,13.97 46.99,13.34 39.37,13.34 33.66,19.05 J24..31-IN.16 | v171.32,21.46 v174.62,24.77 | 66.67,9.53 v66.04,9.53
N$1
  Top 0.203: IC4.14 216.53,89.53 217.17,88.9 229.24,88.9 235.59,95.25 252.73,95.25 258.44,89.53 275.59,89.53 278.13,92.08 IC2.19
N$2  (via drill 0.71)
  Top 0.203: v274.95,96.52 273.69,97.79 222.25,97.79 217.81,93.34 IC4.13
  Bottom 0.203: v274.95,96.52 274.95,93.34 IC2.20
N$3
  Top 0.203: IC4.12 219.07,89.53 229.24,89.53 235.59,95.89 252.73,95.89 258.44,90.17 268.61,90.17 270.51,92.08 IC2.22
N$4  (via drill 0.71)
  Top 0.203: v264.8,96.52 223.52,96.52 220.34,93.34 IC4.11
  Bottom 0.203: v264.8,96.52 267.97,93.34 IC2.23
N$5
  Top 0.203: IC1.14 116.2,94.61 112.39,98.42 66.04,98.42 60.96,93.34 IC6.19
N$6  (via drill 0.71)
  Top 0.203: v117.47,93.34 IC1.13
  Bottom 0.203: v117.47,93.34 100.33,93.34 96.52,89.53 60.96,89.53 58.42,92.08 IC6.20
N$7
  Top 0.203: IC5.11 243.21,89.53 243.84,88.9 277.5,88.9 280.67,92.08 IC2.18
N$8  (via drill 0.71)
  Top 0.203: v113.67,98.42 118.75,93.34 IC1.12 | v55.24,96.52 53.34,94.61 IC6.22
  Bottom 0.203: v113.67,98.42 113.67,99.69 55.24,99.69 v55.24,96.52
N$9
  Top 0.203: IC1.11 120.02,93.34 113.67,99.69 57.15,99.69 50.8,93.34 IC6.23
N$10
  Top 0.203: R9.2 BNC0.CONDUCTOR
N$11
  Top 0.203: R10.2 BNC1.CONDUCTOR
N$12
  Top 0.203: R11.2 BNC2.CONDUCTOR
N$13
  Top 0.203: R12.2 BNC3.CONDUCTOR
N$14
  Top 0.203: R13.2 BNC4.CONDUCTOR
N$15
  Top 0.203: R14.2 BNC5.CONDUCTOR
N$16
  Top 0.203: IC5.12 241.94,89.53 243.21,88.27 279.4,88.27 283.21,92.08 IC2.17
N$17  (via drill 0.71)
  Top 0.203: IC5.13 v240.66,93.34
  Bottom 0.203: v240.66,93.34 261.62,93.34 264.8,90.17 286.38,90.17 288.29,92.08 IC2.15
N$18  (via drill 0.71)
  Top 0.203: v239.52,89.53 IC5.14
  Bottom 0.203: v239.52,89.53 288.29,89.53 290.83,92.08 IC2.14
N$19
  Top 0.203: R15.2 BNC6.CONDUCTOR
N$20
  Top 0.203: R16.2 BNC7.CONDUCTOR
N$21  (via drill 0.71)
  Top 0.203: v99.06,93.34 IC3.11
  Bottom 0.203: v99.06,93.34 80.01,93.34 76.83,90.17 65.41,90.17 63.5,92.08 IC6.18
N$22
  Top 0.203: IC3.12 97.79,93.34 93.34,97.79 70.48,97.79 66.04,93.34 IC6.17
N$23
  Top 0.203: IC3.13 96.52,93.34 92.71,97.16 74.93,97.16 71.12,93.34 IC6.15
N$24
  Top 0.203: BNC0.SHIELD R1.1
N$25
  Top 0.203: IC3.14 95.25,89.53 76.2,89.53 73.66,92.08 IC6.14
N$26
  Top 0.203: BNC8.SHIELD R17.1
N$27
  Top 0.203: BNC1.SHIELD R2.1
N$28
  Top 0.203: BNC2.SHIELD R3.1
N$29
  Top 0.203: BNC3.SHIELD R4.1
N$30
  Top 0.203: BNC9.SHIELD R18.1
N$31
  Top 0.203: BNC10.SHIELD R19.1
N$32
  Top 0.203: BNC11.SHIELD R20.1
N$33
  Top 0.203: BNC12.SHIELD R21.1
N$34
  Top 0.203: BNC13.SHIELD R22.1
N$35
  Top 0.203: BNC14.SHIELD R23.1
N$36
  Top 0.203: BNC15.SHIELD R24.1
N$37
  Top 0.203: BNC4.SHIELD R5.1
N$38
  Top 0.203: R25.2 BNC8.CONDUCTOR
N$39
  Top 0.203: BNC5.SHIELD R6.1
N$40
  Top 0.203: BNC6.SHIELD R7.1
N$41
  Top 0.203: BNC7.SHIELD R8.1
N$42
  Top 0.203: R26.2 BNC9.CONDUCTOR
N$43
  Top 0.203: R27.2 BNC10.CONDUCTOR
N$44
  Top 0.203: R28.2 BNC11.CONDUCTOR
N$45
  Top 0.203: R29.2 BNC12.CONDUCTOR
N$46
  Top 0.203: R30.2 BNC13.CONDUCTOR
N$47
  Top 0.203: R31.2 BNC14.CONDUCTOR
N$48
  Top 0.203: R32.2 BNC15.CONDUCTOR
N$49
  Top 0.635: SUPPLY_+5V.P$1 182.88,96.52 182.88,93.34 F1.2
N$50
  Top 0.203: 0,0.64 0,0 0.64,0
N$51
  Bottom 0.203: 0,0.64 0,0 0.64,0
N$52
  Top 0.203: 0.64,101.6 0,101.6 0,100.97
N$53
  Bottom 0.203: 0.64,101.6 0,101.6 0,100.97
N$54
  Top 0.203: 330.2,100.97 330.2,101.6 329.56,101.6
N$55
  Bottom 0.203: 330.2,100.97 330.2,101.6 329.56,101.6
N$56
  Top 0.203: 329.56,0 330.2,0 330.2,0.64
N$57
  Bottom 0.203: 329.56,0 330.2,0 330.2,0.64
N$97  (via drill 0.71)
  Top 0.203: IC13.14 v236.22,17.78
  Bottom 0.203: v236.22,17.78 250.82,17.78 255.27,22.23 266.06,22.23 267.97,20.32 IC15.23
N$98  (via drill 0.71)
  Top 0.203: IC13.13 v237.49,21.59
  Bottom 0.203: v237.49,21.59 238.76,20.32 252.73,20.32 255.27,22.86 267.97,22.86 270.51,20.32 IC15.22
N$99  (via drill 0.71)
  Top 0.203: v271.14,24.77 275.59,20.32 IC15.20 | IC13.12 v238.89,21.59
  Bottom 0.203: v238.89,21.59 251.46,21.59 254.63,24.77 v271.14,24.77
N$100  (via drill 0.71)
  Top 0.203: v247.01,22.86 250.19,26.04 272.42,26.04 278.13,20.32 IC15.19 | IC13.11 v240.41,22.86
  Bottom 0.203: v240.41,22.86 v247.01,22.86
N$101  (via drill 0.71)
  Top 0.203: v254.63,23.5 255.91,22.23 IC14.11
  Bottom 0.203: v254.63,23.5 287.65,23.5 290.83,20.32 IC15.14
N$102  (via drill 0.71)
  Top 0.203: v286.26,15.88 285.75,16.51 255.91,16.51 254.63,17.78 IC14.12
  Bottom 0.203: v286.26,15.88 288.29,17.78 IC15.15
N$103  (via drill 0.71)
  Top 0.203: v253.37,16.51 IC14.13
  Bottom 0.203: v253.37,16.51 280.67,16.51 283.21,19.05 IC15.17
N$104  (via drill 0.71)
  Top 0.203: IC14.14 v252.09,17.78
  Bottom 0.203: v252.09,17.78 279.4,17.78 280.67,19.05 IC15.18
N$105  (via drill 0.71)
  Top 0.203: R72.1 v197.74,9.53 | v200.91,12.7 IC12.11
  Bottom 0.203: v197.74,9.53 v200.91,12.7
N$106  (via drill 0.71)
  Top 0.203: R71.1 v188.59,8.26 | v202.31,12.7 IC12.12
  Bottom 0.203: v188.59,8.26 197.74,8.26 v202.31,12.7
N$107  (via drill 0.71)
  Top 0.203: v195.96,6.99 187.96,6.99 186.69,8.26 186.69,9.53 R70.1 | v203.71,12.7 IC12.13
  Bottom 0.203: v195.96,6.99 197.23,6.99 201.93,11.43 202.56,11.43 v203.71,12.7
N$108  (via drill 0.71)
  Top 0.203: v197.1,5.71 186.69,5.71 184.15,8.26 184.15,9.53 R69.1 | v205.1,12.7 IC12.14
  Bottom 0.203: v197.1,5.71 197.36,5.71 203.2,11.43 203.84,11.43 v205.1,12.7
N$109
  Top 0.203: IC15.12 321.31,12.06 323.21,13.97 323.21,15.24 J16..23-OUT.8
N$110
  Top 0.203: IC15.10 288.29,12.7 290.19,14.61 303.53,14.61 305.44,12.7 319.4,12.7 320.68,13.97 320.68,15.24 J16..23-OUT.7
N$111
  Top 0.203: IC15.9 285.75,12.7 288.29,15.24 303.53,15.24 305.44,13.34 317.5,13.34 318.13,13.97 318.13,15.24 J16..23-OUT.6
N$112
  Bottom 0.203: IC15.7 280.67,12.7 282.57,14.61 293.37,14.61 297.18,18.41 299.72,18.41 304.8,13.34 314.96,13.34 315.6,13.97 315.6,15.24 J16..23-OUT.5
N$113
  Top 0.203: BNC16.SHIELD R49.1
N$114
  Top 0.203: BNC17.SHIELD R50.1
N$115
  Top 0.203: BNC18.SHIELD R51.1
N$116
  Top 0.203: BNC19.SHIELD R52.1
N$117
  Top 0.203: R53.1 240.66,31.75 240.66,34.92 BNC20.SHIELD
N$118
  Top 0.203: BNC21.SHIELD R54.1
N$119
  Top 0.203: BNC22.SHIELD R55.1
N$120
  Top 0.203: BNC23.SHIELD R56.1
N$121  (via drill 0.71)
  Top 0.203: v287.02,18.29 287.02,20.95 288.29,22.23 298.45,22.23 304.8,15.88 306.07,15.88 J16..23-OUT.1
  Bottom 0.203: v287.02,18.29 284.48,15.88 268.61,15.88 265.43,12.7 IC15.1
N$122  (via drill 0.71)
  Top 0.203: v287.65,15.88 286.38,14.61 285.62,15.24 273.05,15.24 270.51,12.7 IC15.3
  Bottom 0.203: v287.65,15.88 292.1,15.88 294,17.78 294,18.41 294.64,18.41 295.27,19.05 299.72,19.05 304.8,13.97 307.98,13.97 307.98,15.24 J16..23-OUT.2
N$123
  Top 0.203: IC15.4 273.05,11.43 274.95,9.53 320.68,9.53 325.75,14.61 325.75,18.41 324.49,19.68 313.06,19.68 312.42,19.05 312.42,15.88 311.15,15.88 J16..23-OUT.3
N$124  (via drill 0.71)
  Top 0.203: v284.48,13.59 284.48,13.97 283.85,14.61 280.04,14.61 278.13,12.7 IC15.6
  Bottom 0.203: v284.48,13.59 285.12,13.97 293.37,13.97 297.18,17.78 299.72,17.78 304.8,12.7 316.23,12.7 317.5,13.97 317.5,16.51 314.32,16.51 314.32,15.24 J16..23-OUT.4
N$125
  Top 0.203: R57.2 BNC16.CONDUCTOR
N$126
  Top 0.203: R58.2 BNC17.CONDUCTOR
N$127
  Top 0.203: R59.2 BNC18.CONDUCTOR
N$128
  Top 0.203: R60.2 BNC19.CONDUCTOR
N$129
  Top 0.203: R61.2 BNC20.CONDUCTOR
N$130
  Top 0.203: R62.2 BNC21.CONDUCTOR
N$131
  Top 0.203: R63.2 BNC22.CONDUCTOR
N$132
  Top 0.203: R64.2 BNC23.CONDUCTOR
N$133
  Top 0.203: R65.2 J16..23-IN.1
N$134
  Top 0.203: R66.2 J16..23-IN.2
N$135
  Top 0.203: R67.2 J16..23-IN.3
N$136
  Top 0.203: R68.2 J16..23-IN.4
N$137
  Top 0.203: R69.2 J16..23-IN.5
N$138
  Top 0.203: R70.2 J16..23-IN.6
N$139
  Top 0.203: R71.2 J16..23-IN.7
N$140
  Top 0.203: R72.2 J16..23-IN.8
N$141  (via drill 0.71)
  Top 0.203: v174.62,20.32 174.62,10.16 173.99,10.16 173.99,9.53 R65.1 | v175.9,23.5 184.15,23.5 v192.41,31.75 | v203.2,42.55 v214.63,31.11 | v221.62,16.51 IC11.14
  Bottom 0.203: v174.62,20.32 176.53,22.23 176.53,22.86 v175.9,23.5 | v192.41,31.75 v203.2,42.55 | v214.63,31.11 214.63,23.5 v221.62,16.51
N$142  (via drill 0.71)
  Top 0.203: v171.45,18.41 171.45,8.89 172.09,8.26 175.26,8.26 175.26,9.53 R66.1 | v175.26,22.23 v190.5,22.23 | v196.22,22.23 196.22,19.68 199.39,16.51 220.34,16.51 IC11.13
  Bottom 0.203: v171.45,18.41 v175.26,22.23 | v190.5,22.23 v196.22,22.23
N$143  (via drill 0.71)
  Top 0.203: v177.16,5.71 177.8,6.35 177.8,9.53 R67.1 | v205.74,8.26 v215.9,8.26 | v219.2,11.43 IC11.12
  Bottom 0.203: v177.16,5.71 179.71,3.17 204.47,3.17 207.01,5.71 207.01,6.99 v205.74,8.26 | v215.9,8.26 v219.2,11.43
N$144  (via drill 0.71)
  Top 0.203: v198.75,5.71 197.49,4.45 185.42,4.45 181.61,8.26 181.61,9.53 R68.1 | v217.81,12.7 IC11.11
  Bottom 0.203: v198.75,5.71 204.47,11.43 216.53,11.43 v217.81,12.7
N$145  (via drill 0.71)
  Top 0.203: v78.74,7.62 107.31,7.62 110.49,10.79 v110.49,15.88 | v76.2,10.16 IC18.14
  Bottom 0.203: v78.74,7.62 v76.2,10.16 | v110.49,15.88 113.67,15.88 116.84,19.05 IC20.19
N$146  (via drill 0.71)
  Top 0.203: v104.14,24.13 110.49,24.13 114.3,20.32 IC20.20 | IC18.13 v74.93,16.51
  Bottom 0.203: v74.93,16.51 86.36,16.51 88.9,19.05 93.34,19.05 93.98,18.41 98.42,18.41 v104.14,24.13
N$147  (via drill 0.71)
  Top 0.203: v100.97,11.43 v105.41,15.88 | v73.66,11.43 IC18.12
  Bottom 0.203: v73.66,11.43 74.3,11.43 74.93,12.06 85.72,12.06 86.36,11.43 v100.97,11.43 | v105.41,15.88 107.95,18.41 107.95,19.05 109.22,19.05 IC20.22
N$148  (via drill 0.71)
  Top 0.203: IC18.11 v72.39,12.7
  Bottom 0.203: v72.39,12.7 85.09,12.7 87,14.61 102.23,14.61 106.68,19.05 IC20.23
N$149  (via drill 0.71)
  Top 0.203: IC19.11 v86.36,12.7
  Bottom 0.203: v86.36,12.7 102.23,12.7 104.14,14.61 113.03,14.61 116.2,17.78 118.11,17.78 119.38,19.05 IC20.18
N$150  (via drill 0.71)
  Top 0.203: IC19.12 v87.63,16.51
  Bottom 0.203: v87.63,16.51 88.9,15.24 96.52,15.24 103.5,22.23 120.02,22.23 121.92,20.32 IC20.17
N$151  (via drill 0.71)
  Top 0.203: IC19.13 v89.03,16.51
  Bottom 0.203: v89.03,16.51 95.25,16.51 95.89,15.88 96.52,15.88 103.5,22.86 124.46,22.86 127,20.32 IC20.15
N$152
  Top 0.203: IC19.14 90.42,16.51 93.98,16.51 102.87,25.4 124.46,25.4 129.54,20.32 IC20.14
N$153
  Top 0.203: R96.1 28.57,10.79 34.29,16.51 37.47,16.51 IC17.11
N$154  (via drill 0.71)
  Top 0.203: v24.77,9.53 R95.1 | v38.73,12.7 IC17.12
  Bottom 0.203: v24.77,9.53 35.56,9.53 v38.73,12.7
N$155  (via drill 0.71)
  Top 0.203: v35.56,8.26 24.13,8.26 22.86,9.53 22.86,10.79 R94.1 | v40.01,11.43 IC17.13
  Bottom 0.203: v35.56,8.26 38.73,11.43 v40.01,11.43
N$156
  Top 0.203: R93.1 18.41,10.79 18.41,20.32 24.77,26.67 27.94,26.67 33.66,20.95 33.66,18.41 34.92,17.14 40.64,17.14 41.27,16.51 IC17.14
N$157
  Top 0.203: IC20.7 119.38,11.43 121.92,8.89 126.36,8.89 127,8.26 152.4,8.26 158.12,13.97 158.12,15.24 J24..31-OUT.8
N$158
  Top 0.203: IC20.9 124.46,11.43 127,8.89 150.5,8.89 155.57,13.97 155.57,15.24 J24..31-OUT.7
N$159
  Top 0.203: IC20.10 127,11.43 128.91,9.53 148.59,9.53 153.03,13.97 153.03,15.24 J24..31-OUT.6
N$160
  Top 0.203: IC20.12 132.08,12.7 149.22,12.7 150.5,13.97 150.5,15.24 J24..31-OUT.5
N$161
  Top 0.203: BNC24.SHIELD R73.1
N$162
  Top 0.203: BNC25.SHIELD R74.1
N$163
  Top 0.203: BNC26.SHIELD R75.1
N$164
  Top 0.203: BNC27.SHIELD R76.1
N$165
  Top 0.203: BNC28.SHIELD R77.1
N$166
  Top 0.203: BNC29.SHIELD R78.1
N$167
  Top 0.203: BNC30.SHIELD R79.1
N$168
  Top 0.203: BNC31.SHIELD R80.1
N$169
  Top 0.203: IC20.6 116.84,12.7 119.38,15.24 J24..31-OUT.1
N$170
  Bottom 0.203: IC20.4 111.76,12.7 113.67,14.61 139.06,14.61 140.34,13.34 142.24,13.34 142.88,13.97 142.88,15.24 J24..31-OUT.2
N$171
  Bottom 0.203: IC20.3 109.22,11.43 111.12,9.53 140.97,9.53 145.41,13.97 145.41,15.24 J24..31-OUT.3
N$172
  Bottom 0.203: IC20.1 104.14,11.43 106.68,8.89 142.88,8.89 147.96,13.97 147.96,15.24 J24..31-OUT.4
N$173
  Top 0.203: R81.2 BNC24.CONDUCTOR
N$174
  Top 0.203: R82.2 BNC25.CONDUCTOR
N$175
  Top 0.203: R83.2 BNC26.CONDUCTOR
N$176
  Top 0.203: R84.2 BNC27.CONDUCTOR
N$177
  Top 0.203: R85.2 BNC28.CONDUCTOR
N$178
  Top 0.203: R86.2 BNC29.CONDUCTOR
N$179
  Top 0.203: R87.2 BNC30.CONDUCTOR
N$180
  Top 0.203: R88.2 BNC31.CONDUCTOR
N$181
  Top 0.203: R89.2 J24..31-IN.1
N$182
  Top 0.203: R90.2 J24..31-IN.2
N$183
  Top 0.203: R91.2 J24..31-IN.3
N$184
  Top 0.203: R92.2 J24..31-IN.4
N$185
  Top 0.203: R93.2 J24..31-IN.5
N$186
  Top 0.203: R94.2 J24..31-IN.6
N$187
  Top 0.203: R95.2 J24..31-IN.7
N$188
  Top 0.203: R96.2 J24..31-IN.8
N$189  (via drill 0.71)
  Top 0.203: v13.97,5.71 10.16,9.53 10.16,10.79 R89.1 | v56.52,12.7 IC16.14
  Bottom 0.203: v13.97,5.71 49.53,5.71 v56.52,12.7
N$190  (via drill 0.71)
  Top 0.203: v15.24,6.99 12.7,9.53 12.7,10.79 R90.1 | v55.12,12.7 IC16.13
  Bottom 0.203: v15.24,6.99 25.4,6.99 26.04,6.35 48.9,6.35 v55.12,12.7
N$191  (via drill 0.71)
  Top 0.203: v15.24,9.53 15.24,10.79 R91.1 | v53.72,12.7 IC16.12
  Bottom 0.203: v15.24,9.53 23.5,9.53 26.04,6.99 46.35,6.99 52.07,12.7 v53.72,12.7
N$192  (via drill 0.71)
  Top 0.203: v48.9,8.26 48.9,4.45 17.78,4.45 17.78,10.79 R92.1 | v52.07,11.43 52.07,12.06 52.7,12.7 IC16.11
  Bottom 0.203: v48.9,8.26 v52.07,11.43
W+5V  (via drill 0.71)
  Top 0.635: 93.34,19.68 IC19.1 | 93.34,19.68 C20.2 | 79.38,20.32 79.38,19.68 IC18.1 | 79.38,20.32 C23.2 | 44.45,14.61 IC17.16 | 44.45,14.61 C22.2 | 59.69,14.61 IC16.16 | 59.69,14.61 C21.2 | v46.99,14.61 44.45,14.61 | v60.33,14.61 59.69,14.61 | v80.01,20.32 79.38,20.32 | v93.98,19.68 93.34,19.68 | 248.92,14.61 IC14.1 | 248.92,14.61 C14.2 | 208.28,14.61 IC12.16 | 208.28,14.61 C11.2 | 230.5,12.06 C13.2 | 227.33,12.06 230.5,12.06 | 227.33,12.06 C12.2 | 225.43,13.97 224.16,13.97 IC11.16 | 225.43,13.97 227.33,12.06 | 230.5,12.06 232.41,13.97 233.68,13.97 IC13.1 | v212.09,14.61 208.28,14.61 | v225.43,14.61 225.43,13.97 | v243.84,14.61 248.92,14.61 | 92.08,85.72 92.08,86.36 IC3.1 | 92.08,85.72 C7.2 | 113.03,85.72 113.03,86.36 IC1.1 | 113.03,85.72 C6.2 | v91.44,85.72 92.08,85.72 | v112.39,85.72 113.03,85.72 | 213.36,85.72 213.36,86.36 IC4.1 | 213.36,85.72 C1.2 | 236.22,85.72 236.22,86.36 IC5.1 | 236.22,85.72 C2.2 | v212.72,85.72 213.36,85.72 | v235.59,85.72 236.22,85.72 | 185.42,60.33 v185.42,61.59 | 185.42,60.33 185.42,59.05 | 185.42,59.05 185.42,55.24 J1.2 | v117.47,79.38 161.93,79.38 182.25,59.05 185.42,59.05 | v212.09,29.84 212.09,31.11 189.87,53.34 189.87,55.88 185.42,60.33 | v83.82,29.84 v80.01,26.04 | v79.38,29.84 79.38,30.48 77.47,32.38 72.39,32.38 v71.75,31.75
  Bottom 0.635: v46.99,14.61 v60.33,14.61 60.96,14.61 69.22,22.86 70.48,22.86 73.03,20.32 v80.01,20.32 | v93.98,19.68 80.64,19.68 v80.01,20.32 | v243.84,14.61 v225.43,14.61 v212.09,14.61 v212.09,29.84 | v235.59,85.72 v212.72,85.72 209.55,85.72 v185.42,61.59 | v117.47,79.38 112.39,84.45 v112.39,85.72 v91.44,85.72 91.44,78.11 88.27,74.93 88.27,55.24 69.22,36.2 69.22,34.29 v71.75,31.75 | v80.01,26.04 v80.01,20.32 | v79.38,29.84 v83.82,29.84
WGND  (via drill 0.71)
  Top 0.635: IC18.2 C23.1 77.47,22.86 | 77.47,22.86 71.12,22.86 v69.85,21.59 IC18.8 | C20.1 IC19.2 | C20.1 83.82,22.23 | 83.82,22.23 IC19.8 | 77.47,22.86 77.47,24.13 81.92,24.13 83.82,22.23 | IC16.15 C21.1 57.78,11.43 | IC17.15 C22.1 42.55,10.16 | 42.55,10.16 37.47,10.16 34.92,12.7 IC17.9 | 48.26,13.34 45.09,10.16 42.55,10.16 | 48.26,13.34 48.9,13.97 50.16,13.97 IC16.9 | 57.78,11.43 53.98,11.43 52.7,10.16 51.44,10.16 48.26,13.34 | v57.78,10.16 57.78,11.43 | IC12.15 C11.1 206.38,11.43 204.47,11.43 | 204.47,11.43 200.03,11.43 198.75,12.7 IC12.9 198.75,15.24 197.49,15.24 194.94,17.78 194.94,31.11 184.15,41.91 184.15,51.44 J1.21 184.15,52.7 184.15,53.98 182.25,53.98 J1.3 | 215.26,13.97 213.36,13.97 209.55,10.16 205.74,10.16 204.47,11.43 | IC14.2 C14.1 250.82,11.43 | 250.82,11.43 257.18,11.43 258.44,12.7 IC14.8 | IC11.15 C12.1 222.88,10.16 | IC13.2 C13.1 234.95,10.16 | 240.03,10.16 242.57,12.7 IC13.8 | 240.03,10.16 234.95,10.16 | 234.95,10.16 222.88,10.16 | 250.82,11.43 250.82,10.16 240.03,10.16 | 215.26,13.97 215.26,12.06 217.17,10.16 222.88,10.16 | 215.26,13.97 IC11.9 | IC3.2 C7.1 95.25,83.82 97.16,81.92 | 101.6,84.45 99.06,81.92 97.16,81.92 | 101.6,84.45 IC3.8 | IC1.2 C6.1 114.94,81.92 | 122.56,84.45 118.75,80.64 116.2,80.64 114.94,81.92 | 122.56,84.45 IC1.8 | 101.6,84.45 104.14,81.92 114.94,81.92 | IC4.2 C1.1 215.26,83.19 v214,81.92 | IC5.2 C2.1 238.12,82.55 | 225.43,85.72 231.78,85.72 234.95,82.55 238.12,82.55 | 225.43,85.72 222.88,85.72 IC4.8 | 238.12,82.55 243.84,82.55 245.75,84.45 IC5.8 | v219.07,81.92 221.62,81.92 225.43,85.72 | 122.56,84.45 126.36,80.64 161.93,80.64 182.25,60.33 v182.88,60.33 | 97.16,81.92 v96.52,81.28
  Top 0.635: v91.44,26.04 C20.1
  Bottom 0.635: v69.85,21.59 69.22,21.59 v57.78,10.16 | 182.88,56.52 186.69,56.52 187.32,55.88 187.32,54.61 J1.1 188.59,55.24 188.59,56.52 v214,81.92 v219.07,81.92 | 182.88,56.52 182.88,55.24 J1.3 | 182.88,56.52 v182.88,60.33 | v91.44,26.04 91.44,32.38 89.53,34.29 89.53,74.3 v96.52,81.28

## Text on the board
Top: - 5V + | 1A | Ad-Win Buffer, Digital J.Thywissen Lab Rev:A | University of Toronto, Physics, Quantum Optics Labs
tNames: F1
Target: Ad-Win Buffer, Digital | J. Thywissen Lab | Stummer/Myrskog Feb '04 | B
